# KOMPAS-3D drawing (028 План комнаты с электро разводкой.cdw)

Views: Вид 1, Вид 2, Вид 3, Вид 4, Вид 5
Referenced files in \\Promsrv4\спо\002_Проекты (ПСПД)\г. Южно-Сахалинск\Работы по ИТП (COWI) 2014\ПРОЕКТЫ ИТП\Украинская, 9\: План комнаты где ставить элеватор.cdw
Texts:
  ПСПД-0000-2015
  План размещения оборудования и внешних проводок
  Шкаф ШСУ
  (подвал)
  1. Трубопроводы условно разнесены от стен и условно разнесены друг от друга.
  2. Место установки щита узла учета уточняется при монтаже.
  3. Место подключению к силовому щиту  220В уточняется при монтаже.
  4. Назначение кабелей К1...К15 см. кабельный журнал.
  5. Кабели прокладываются в гибкой гофрированной трубе.
  6. Кабельная трасса: гофру вести по стене и потолку, крепления выполнить клипсами.
  Т1, Ду65
  Т2, Ду65
  Линия проводки, общее изображение ГОСТ 21.614-88
  Стили документа
  ПСПД-0093-2014-
  План размещения оборудования
  и внешних проводок
  ЗАО "ПромСервис"
  г. Димитровград
  Разраб.
  Пров.
  Чертеж строит. Первый лист. ГОСТ Р 21.1101-2009 Ф4.
  Лит-Масса-Масштаб
  Материал-Предприятие
  Масштаб
  Изм.
  Кол.уч.
  .Лист
  №док.
  Подп.
  Дата
  Стадия
  Лист
  Листов
  Изменение
  Номер документа
  Подпись
  Обозначение документа
  Наименование изделия и наименование документа
  Должность подписавшего
  Масса изделия
  Порядковый номер листа
  Общее количество листов в документе
  Индекс предприятия, выпускающего документ
  Инв. № подл.
  Подп. и дата
  Взам. инв. №
  Инвентарный номер подлинника
  Подпись принявшего подлинник на хранение
  Инвентарный номер подлинника, взамен которого выпущен данный подлинник
Dimensions and other numbers on the sheet: 1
